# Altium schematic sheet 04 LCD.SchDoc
size 513 x 386 mm
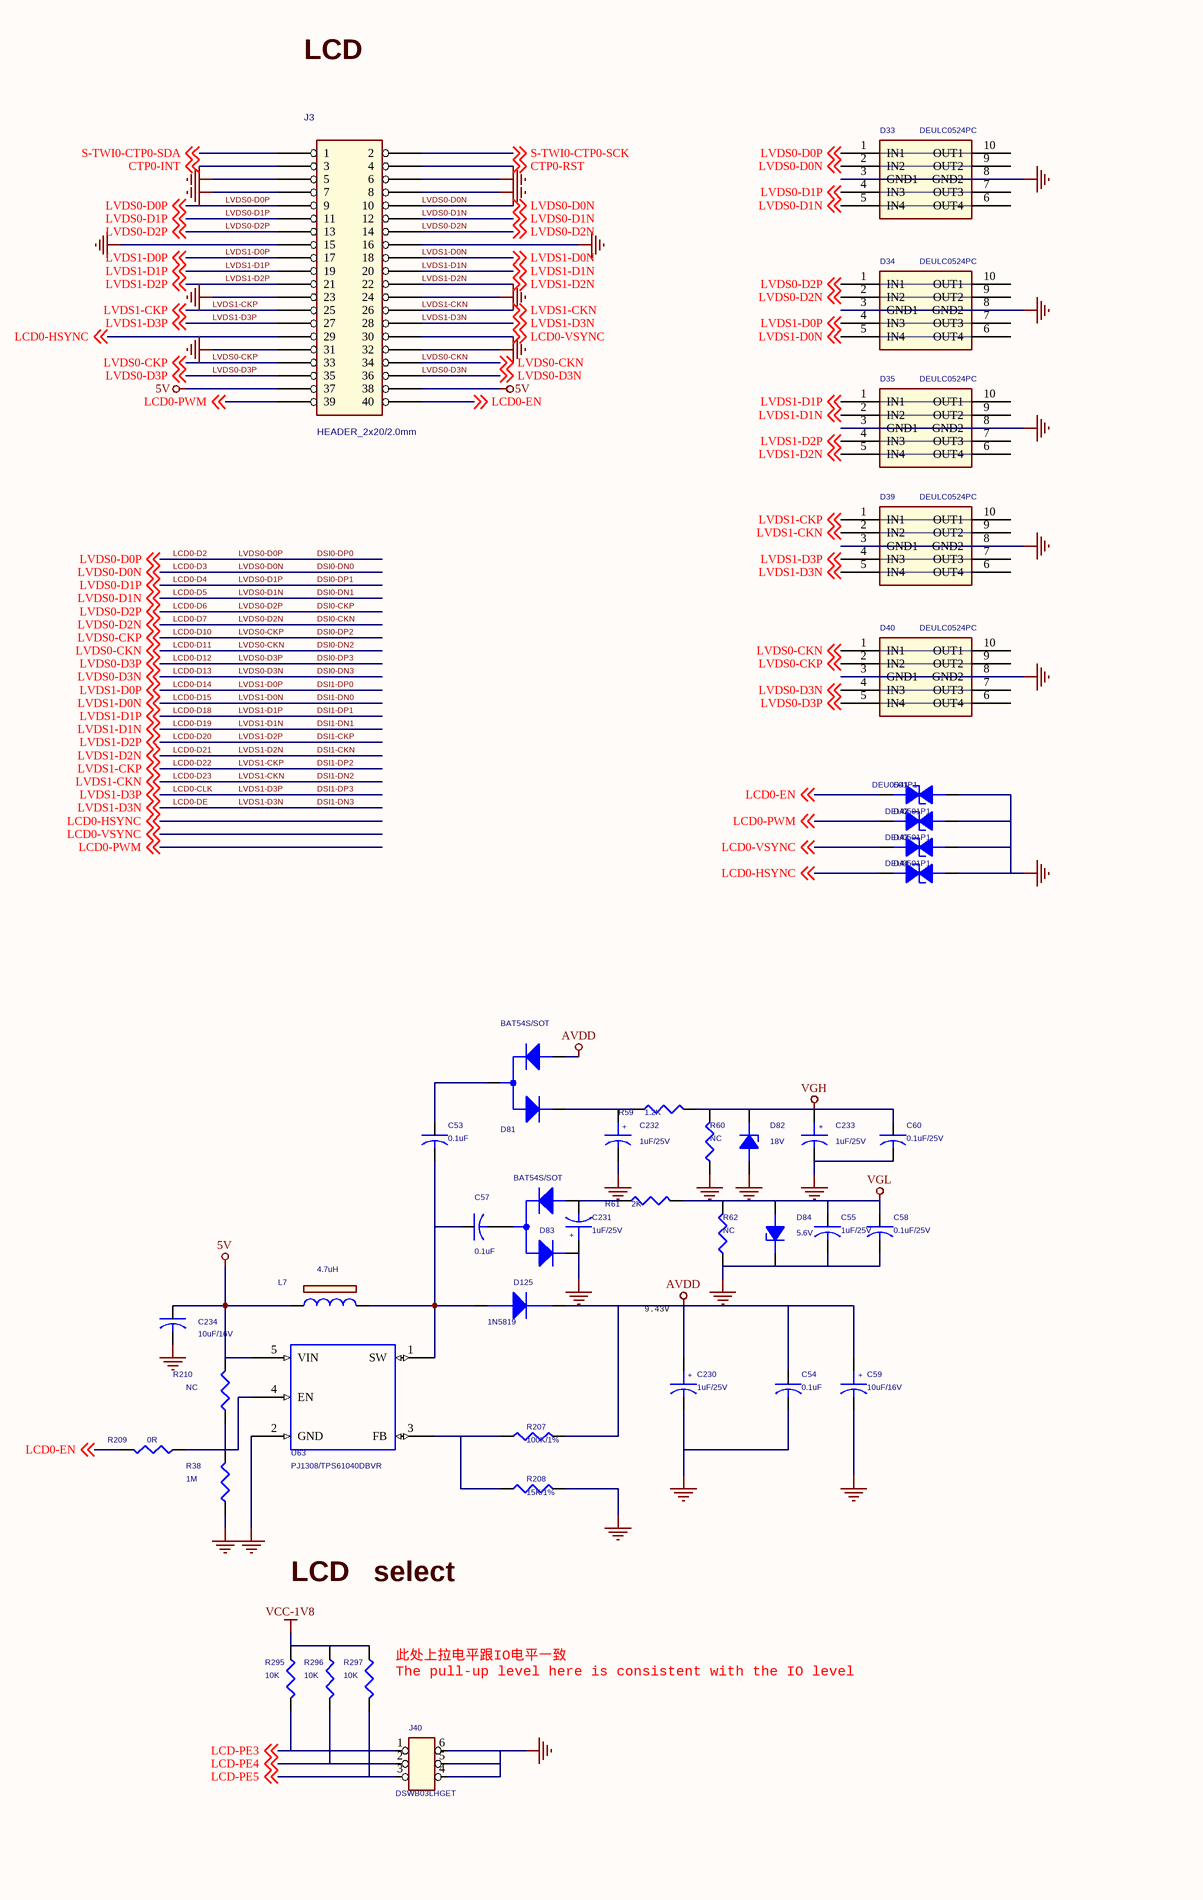
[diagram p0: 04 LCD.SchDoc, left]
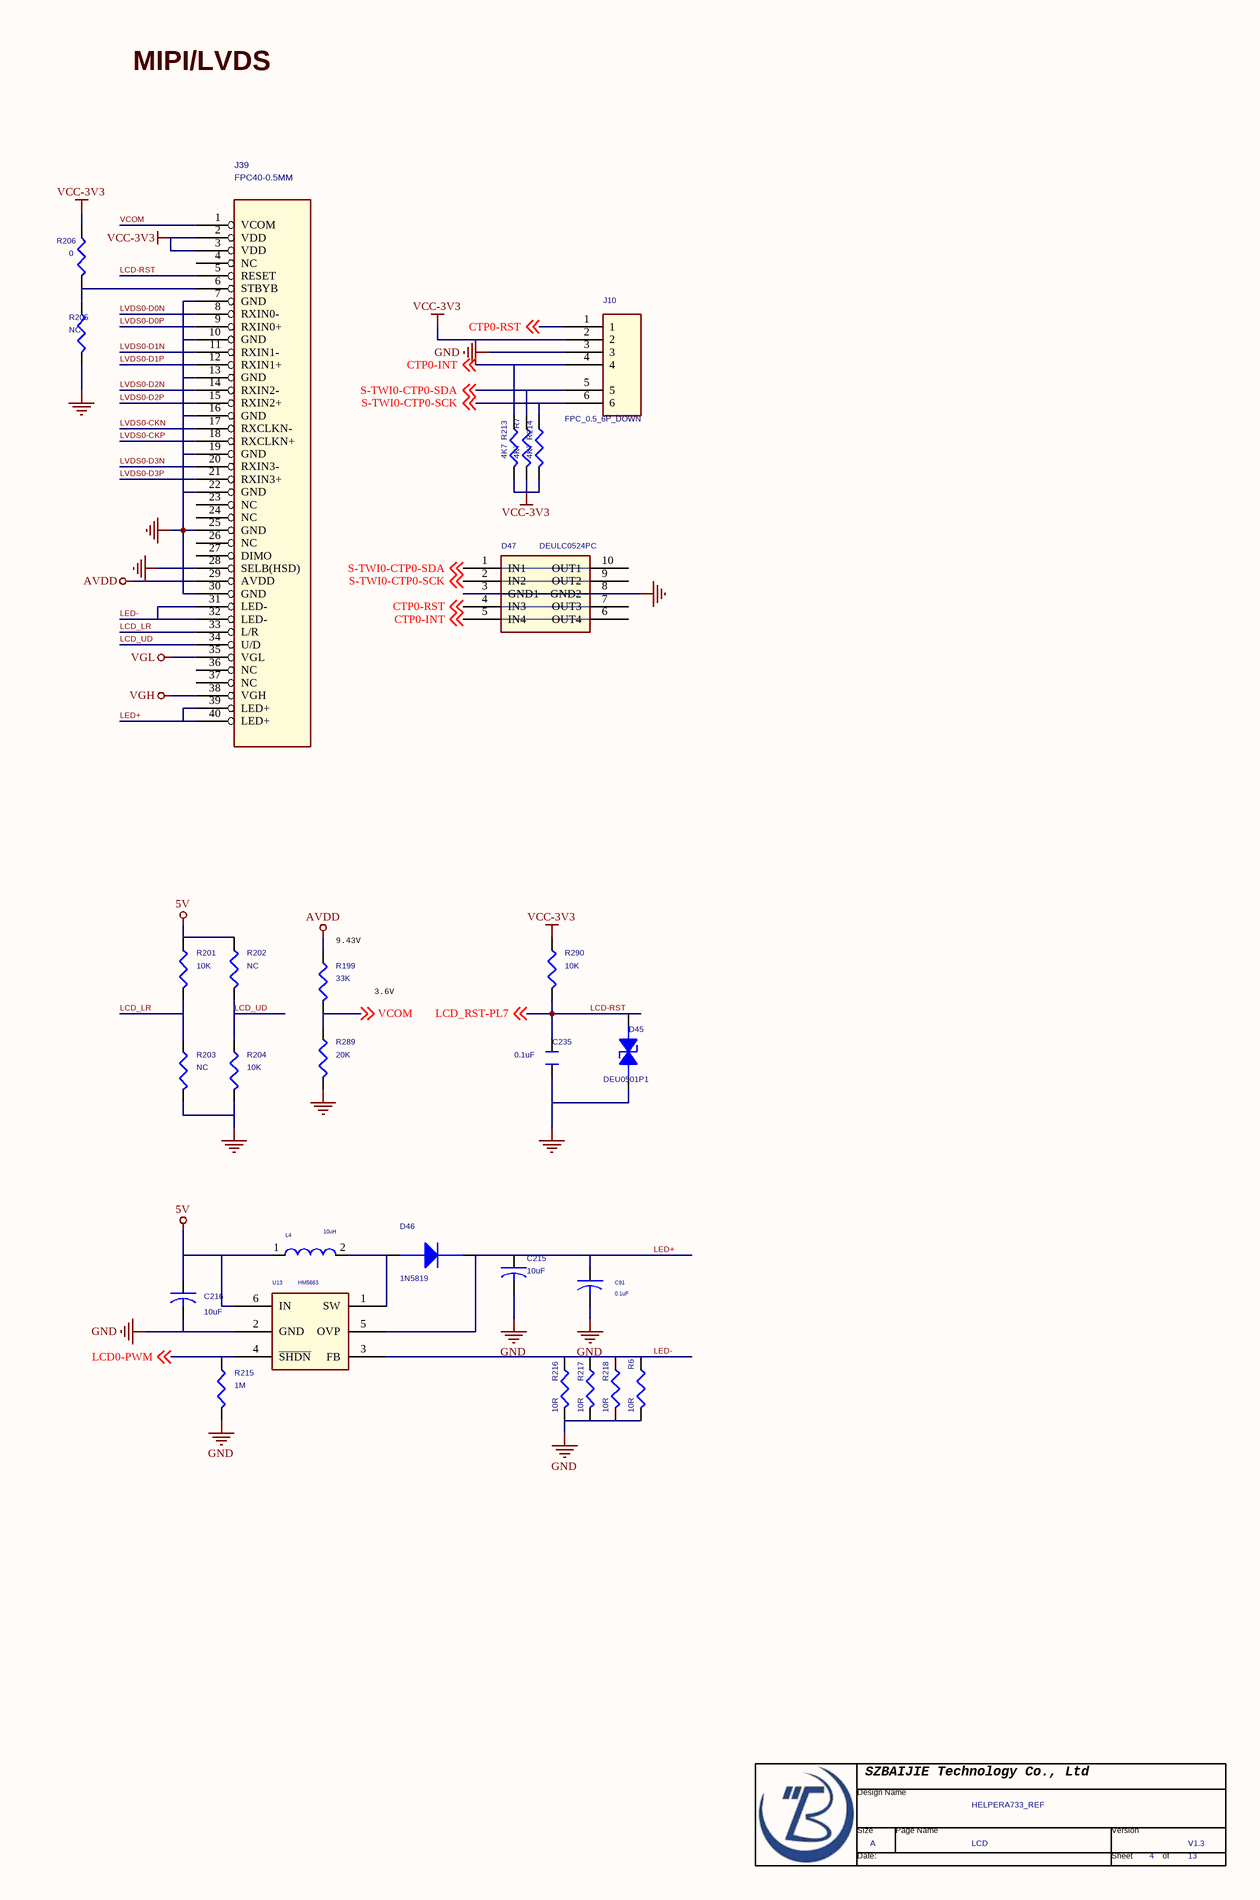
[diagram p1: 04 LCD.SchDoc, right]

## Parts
*  Page Count: 13  Page Number: 4  Page Size: A  Title: HELPERA733_REF  RevCode: V1.3  Doc: LCD  (hidden comment: TitleBlock0-BJ)  (graphical)
C53  0.1uF  [C0402]
C54  0.1uF  [C0402]
C55  1uF/25V  [C0805]
C57  0.1uF  [C0402]
C58  0.1uF/25V  [C0402]
C59  10uF/16V  [C0805]
C60  0.1uF/25V  [C0402]
C91  0.1uF  [C0402]
C215  10uF  [C0603]
C216  10uF  [C0603]
C230  1uF/25V  [C0805]
C231  1uF/25V  [C0805]
C232  1uF/25V  [C0805]
C233  1uF/25V  [C0805]
C234  10uF/16V  [C0805]
C235  0.1uF  [C0402]
D33  DEULC0524PC  [DFN2510-10_L2.5-W1.0-P0.50-BL]
D34  DEULC0524PC  [DFN2510-10_L2.5-W1.0-P0.50-BL]
D35  DEULC0524PC  [DFN2510-10_L2.5-W1.0-P0.50-BL]
D39  DEULC0524PC  [DFN2510-10_L2.5-W1.0-P0.50-BL]
D40  DEULC0524PC  [DFN2510-10_L2.5-W1.0-P0.50-BL]
D41  DEU0501P1  [ESD0402]
D42  DEU0501P1  [ESD0402]
D43  DEU0501P1  [ESD0402]
D44  DEU0501P1  [ESD0402]
D45  DEU0501P1  [ESD0402]
D46  1N5819  [SOD323]
D47  DEULC0524PC  [DFN2510-10_L2.5-W1.0-P0.50-BL]
D81  BAT54S/SOT  [SOT23]
D82  18V  [D0805]
D83  BAT54S/SOT  [SOT23]
D84  5.6V  [D0805]
D125  1N5819  [D0805]
J3  HEADER_2x20/2.0mm  [HDR2X20/2.0]
J10  FPC_0.5_6P_DOWN  [FPC_0.5_6P_DOWN]
J39  FPC40-0.5MM  [FPC40-0.5MM-UP]
J40  DSWB03LHGET  [SW-TH-DSWB03LHGET]
L4  10uH  [4018]
L7  4.7uH  [4018]
R6  10R  [R0402]
R7  4K7  [R0402]
R38  1M  [R0402]
R59  1.2K  [R0402]
R60  NC  [R0402]
R61  2K  [R0402]
R62  NC  [R0402]
R199  33K  [R0402]
R201  10K  [R0402]
R202  NC  [R0402]
R203  NC  [R0402]
R204  10K  [R0402]
R205  NC  [R0402]
R206  0  [R0402]
R207  100K/1%  [R0402]
R208  15K/1%  [R0402]
R209  0R  [R0402]
R210  NC  [R0402]
R213  4K7  [R0402]
R214  4K7  [R0402]
R215  1M  [R0402]
R216  10R  [R0402]
R217  10R  [R0402]
R218  10R  [R0402]
R289  20K  [R0402]
R290  10K  [R0402]
R295  10K  [R0402]
R296  10K  [R0402]
R297  10K  [R0402]
U13  HM5663  [SOT89-5]
U63  PJ1308/TPS61040DBVR  [SOT23-5]

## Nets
5V: C216.1 C234.1 J3.37 J3.38 L4.1 L7.1 R201.1 R202.1 R210.2 U13.6(IN) U63.5(VIN)
AVDD: C54.1 C59.1 C230.1 D81.1 D125.2(CATHODE) J39.29(AVDD) R199.1 R207.2
GND: C54.2 C55.2 C58.2 C59.2 C60.2 C91.2 C215.2 C216.2 C230.2 C231.1 C232.2 C233.2 C234.2 C235.1 D33.3(GND1) D33.8(GND2) D34.3(GND1) D34.8(GND2) D35.3(GND1) D35.8(GND2) D39.3(GND1) D39.8(GND2) D40.3(GND1) D40.8(GND2) D41.2(CATHODE) D42.2(CATHODE) D43.2(CATHODE) D44.2(CATHODE) D45.2(CATHODE) D47.3(GND1) D47.8(GND2) D82.1(ANODE) D83.2 D84.2(CATHODE) J3.5 J3.6 J3.7 J3.8 J3.15 J3.16 J3.23 J3.24 J3.31 J3.32 J10.3 J39.7(GND) J39.10(GND) J39.13(GND) J39.16(GND) J39.19(GND) J39.22(GND) J39.25(GND) J39.28(SELB(HSD)) J39.30(GND) J40.4 J40.5 J40.6 R6.2 R38.1 R60.1 R62.1 R203.2 R204.2 R205.2 R208.2 R215.2 R216.2 R217.2 R218.2 R289.2 U13.2(GND) U63.2(GND)
VCC-1V8: R295.1 R296.1 R297.1
VCC-3V3: J10.2 J39.2(VDD) J39.3(VDD) R7.2 R206.1 R213.2 R214.2 R290.1
VGH: C60.1 C233.1 D82.2(CATHODE) J39.38(VGH) R59.2 R60.2
VGL: C55.1 C58.1 D84.1(ANODE) J39.35(VGL) R61.2 R62.2
CTP0-INT: D47.5(IN4) D47.6(OUT4) J3.3 J10.4 R213.1 ; off-sheet CTP0-INT
CTP0-RST: D47.4(IN3) D47.7(OUT3) J3.4 J10.1 ; off-sheet CTP0-RST
DSI0-CKN: D34.2(IN2) D34.9(OUT2) J3.14 J39.14(RXIN2-) ; off-sheet LVDS0-D2N  [also labelled LCD0-D7, LVDS0-D2N]
DSI0-CKP: D34.1(IN1) D34.10(OUT1) J3.13 J39.15(RXIN2+) ; off-sheet LVDS0-D2P  [also labelled LCD0-D6, LVDS0-D2P]
DSI0-DN0: D33.2(IN2) D33.9(OUT2) J3.10 J39.8(RXIN0-) ; off-sheet LVDS0-D0N  [also labelled LCD0-D3, LVDS0-D0N]
DSI0-DN1: D33.5(IN4) D33.6(OUT4) J3.12 J39.11(RXIN1-) ; off-sheet LVDS0-D1N  [also labelled LCD0-D5, LVDS0-D1N]
DSI0-DN2: D40.1(IN1) D40.10(OUT1) J3.34 J39.17(RXCLKN-) ; off-sheet LVDS0-CKN  [also labelled LCD0-D11, LVDS0-CKN]
DSI0-DN3: D40.4(IN3) D40.7(OUT3) J3.36 J39.20(RXIN3-) ; off-sheet LVDS0-D3N  [also labelled LCD0-D13, LVDS0-D3N]
DSI0-DP0: D33.1(IN1) D33.10(OUT1) J3.9 J39.9(RXIN0+) ; off-sheet LVDS0-D0P  [also labelled LCD0-D2, LVDS0-D0P]
DSI0-DP1: D33.4(IN3) D33.7(OUT3) J3.11 J39.12(RXIN1+) ; off-sheet LVDS0-D1P  [also labelled LCD0-D4, LVDS0-D1P]
DSI0-DP2: D40.2(IN2) D40.9(OUT2) J3.33 J39.18(RXCLKN+) ; off-sheet LVDS0-CKP  [also labelled LCD0-D10, LVDS0-CKP]
DSI0-DP3: D40.5(IN4) D40.6(OUT4) J3.35 J39.21(RXIN3+) ; off-sheet LVDS0-D3P  [also labelled LCD0-D12, LVDS0-D3P]
DSI1-CKN: D35.5(IN4) D35.6(OUT4) J3.22 ; off-sheet LVDS1-D2N  [also labelled LCD0-D21, LVDS1-D2N]
DSI1-CKP: D35.4(IN3) D35.7(OUT3) J3.21 ; off-sheet LVDS1-D2P  [also labelled LCD0-D20, LVDS1-D2P]
DSI1-DN0: D34.5(IN4) D34.6(OUT4) J3.18 ; off-sheet LVDS1-D0N  [also labelled LCD0-D15, LVDS1-D0N]
DSI1-DN1: D35.2(IN2) D35.9(OUT2) J3.20 ; off-sheet LVDS1-D1N  [also labelled LCD0-D19, LVDS1-D1N]
DSI1-DN2: D39.2(IN2) D39.9(OUT2) J3.26 ; off-sheet LVDS1-CKN  [also labelled LCD0-D23, LVDS1-CKN]
DSI1-DN3: D39.5(IN4) D39.6(OUT4) J3.28 ; off-sheet LVDS1-D3N  [also labelled LCD0-DE, LVDS1-D3N]
DSI1-DP0: D34.4(IN3) D34.7(OUT3) J3.17 ; off-sheet LVDS1-D0P  [also labelled LCD0-D14, LVDS1-D0P]
DSI1-DP1: D35.1(IN1) D35.10(OUT1) J3.19 ; off-sheet LVDS1-D1P  [also labelled LCD0-D18, LVDS1-D1P]
DSI1-DP2: D39.1(IN1) D39.10(OUT1) J3.25 ; off-sheet LVDS1-CKP  [also labelled LCD0-D22, LVDS1-CKP]
DSI1-DP3: D39.4(IN3) D39.7(OUT3) J3.27 ; off-sheet LVDS1-D3P  [also labelled LCD0-CLK, LVDS1-D3P]
LCD0-EN: D41.1(ANODE) J3.40 R209.2 ; off-sheet LCD0-EN
LCD0-HSYNC: D44.1(ANODE) J3.29 ; off-sheet LCD0-HSYNC
LCD0-PWM: D42.1(ANODE) J3.39 R215.1 U13.4(~{SHDN}) ; off-sheet LCD0-PWM
LCD0-VSYNC: D43.1(ANODE) J3.30 ; off-sheet LCD0-VSYNC
LCD-PE3: J40.1 R295.2 ; off-sheet LCD-PE3
LCD-PE4: J40.2 R296.2 ; off-sheet LCD-PE4
LCD-PE5: J40.3 R297.2 ; off-sheet LCD-PE5
LCD-RST: C235.2 D45.1(ANODE) J39.5(RESET) R290.2 ; off-sheet LCD_RST-PL7  [also labelled LCD_RST-PL7]
LCD_LR: J39.33(L/R) R201.2 R203.1
LCD_UD: J39.34(U/D) R202.2 R204.1
LED+: C91.1 C215.1 D46.2(CATHODE) J39.39(LED+) J39.40(LED+) U13.5(OVP)
LED-: J39.31(LED-) J39.32(LED-) R6.1 R216.1 R217.1 R218.1 U13.3(FB)
S-TWI0-CTP0-SCK: D47.2(IN2) D47.9(OUT2) J3.2 J10.6 R214.1 ; off-sheet S-TWI0-CTP0-SCK
S-TWI0-CTP0-SDA: D47.1(IN1) D47.10(OUT1) J3.1 J10.5 R7.1 ; off-sheet S-TWI0-CTP0-SDA
VCOM: J39.1(VCOM) R199.2 R289.1 ; off-sheet VCOM
NetC53_1: C53.1 D81.3
NetC53_2: C53.2 C57.1 D125.1(ANODE) L7.2 U63.1(SW)
NetC57_2: C57.2 D83.3
NetC231_2: C231.2 D83.1 R61.1
NetC232_1: C232.1 D81.2 R59.1
NetD46_1: D46.1(ANODE) L4.2 U13.1(SW)
NetJ39_6: J39.6(STBYB) R205.1 R206.2
NetR38_2: R38.2 R209.1 R210.1 U63.4(EN)
NetR207_1: R207.1 R208.1 U63.3(FB)

Not connected (* = marked no-connect by the designer): J39 4(NC) 23(NC) 24(NC) 26(NC) 27(DIMO) 36(NC) 37(NC)

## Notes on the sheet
- LCD
- MIPI/LVDS
- (near R199) 9.43V
- 3.6V
- 9.43V
- LCD   select
- (near R297) 此处上拉电平跟IO电平一致
  The pull-up level here is consistent with the IO level

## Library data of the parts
C53-C55 C57 C58 C60 C215 C216 C234 = C_Dup1
C59 C230-C233 = CAP POL
C91 = C
C235 = CAPACITOR_0_Dup1
D33-D35 D39 D40 D47 = rRClamp0524P
D41-D45 = 1_1.5KE100A_Dup1: 1ST PART DESCRIPTION: WILL ESD9B5V Bidirection ESD Protection
D46 D125 = BAS21/SOT_1
D82 D84 = DIODE BREAKDOWN_1
J3 = HEADER 20X2_1: Populate: YES
J10 = connet_0
J39 = HEADER 20X2_3: Populate: YES
J40 = CON4_4
L4 = INDUCTOR_Dup1
L7 = CHOKE TORROID-FERRITE
R6 R7 R199 R201-R208 R213-R218 R289 R290 R295-R297 = R_Dup2
R38 R59-R62 R209 R210 = RESISTOR_Dup1
U13 = PT4110_0
U63 = X9C102/SO_2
